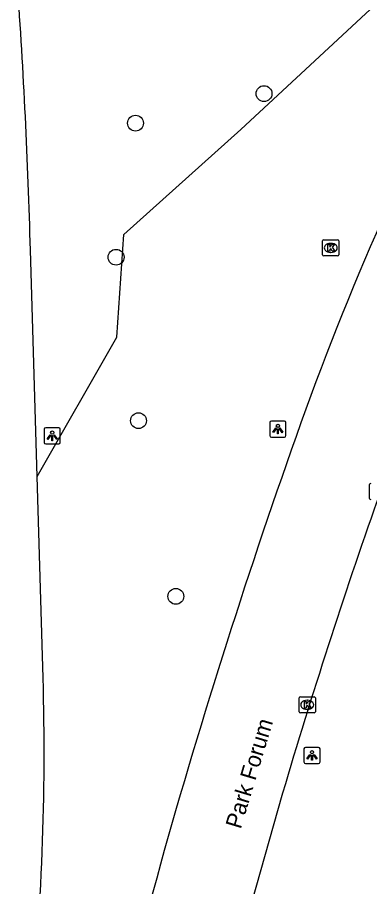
# Model space of a CAD drawing. Extents: x 154324 to 155743, y 382939 to 384183.
# Drawn here: x 155195.7 to 155217.4, y 383375.8 to 383429.5 of the extents above; entities that cross this region are included whole.
import ezdxf

# ---------------------------------------------------------------- set-up
doc = ezdxf.new("R2010")
doc.units = 0
for name, color, linetype in [('IMGEO_Boom', 7, 'Continuous'), ('IMGEO_Groenvoorziening', 7, 'Continuous'), ('IMGEO_Kolk', 7, 'Continuous'), ('IMGEO_Lichtpunt', 7, 'Continuous'), ('IMGEO_Openbare_ruimte_label', 7, 'Continuous'), ('IMGEO_Rijbaan_lokaal_open', 7, 'Continuous'), ('IMGEO_Rijbaan_regionaal_gesloten', 7, 'Continuous')]:
    doc.layers.add(name, color=color, linetype=linetype)

msp = doc.modelspace()

# ---------------------------------------------------------------- linework, layer by layer
at = {"layer": 'IMGEO_Boom'}
for centre in [(155210.882, 383424.797), (155202.942, 383422.968), (155201.746, 383414.682), (155203.128, 383404.578), (155205.432, 383393.717)]:
    msp.add_circle(centre, 0.489, dxfattribs=at)
at = {"layer": 'IMGEO_Groenvoorziening'}
msp.add_lwpolyline([(155196.87, 383401.138), (155201.784, 383409.737), (155202.227, 383416.08), (155209.454, 383422.57), (155218.304, 383430.83), (155232.76, 383449.415), (155225.088, 383476.944)], dxfattribs=at)
at = {"layer": 'IMGEO_Kolk'}
for p, q in [((155214.499, 383414.836), (155214.499, 383415.688)), ((155214.574, 383415.762), (155215.426, 383415.762)), ((155215.5, 383415.688), (155215.5, 383414.836)), ((155214.987, 383415.542), (155215.012, 383415.542)), ((155215.426, 383414.762), (155214.574, 383414.762)), ((155215.01, 383414.982), (155214.985, 383414.982)), ((155217.399, 383399.775), (155217.399, 383400.627)), ((155213.049, 383386.586), (155213.049, 383387.438)), ((155213.124, 383387.512), (155213.976, 383387.512)), ((155213.537, 383387.292), (155213.562, 383387.292)), ((155214.05, 383387.438), (155214.05, 383386.586)), ((155213.56, 383386.732), (155213.535, 383386.732)), ((155213.976, 383386.512), (155213.124, 383386.512))]:
    msp.add_line(p, q, dxfattribs=at)
for points in [[(155214.499, 383414.836), (155214.499, 383415.688)], [(155214.574, 383415.762), (155215.426, 383415.762)], [(155215.5, 383415.688), (155215.5, 383414.836)], [(155214.82, 383415.462), (155214.943, 383415.462), (155214.943, 383415.311), (155215.073, 383415.462), (155215.237, 383415.462), (155215.091, 383415.311), (155215.244, 383415.062), (155215.092, 383415.062), (155215.007, 383415.226), (155214.943, 383415.159), (155214.943, 383415.062), (155214.82, 383415.062), (155214.82, 383415.462)], [(155215.426, 383414.762), (155214.574, 383414.762)], [(155217.399, 383399.775), (155217.399, 383400.627)], [(155213.049, 383386.586), (155213.049, 383387.438)], [(155213.124, 383387.512), (155213.976, 383387.512)], [(155213.37, 383387.212), (155213.493, 383387.212), (155213.493, 383387.061), (155213.623, 383387.212), (155213.787, 383387.212), (155213.641, 383387.061), (155213.794, 383386.812), (155213.642, 383386.812), (155213.557, 383386.976), (155213.493, 383386.909), (155213.493, 383386.812), (155213.37, 383386.812), (155213.37, 383387.212)], [(155214.05, 383387.438), (155214.05, 383386.586)], [(155213.976, 383386.512), (155213.124, 383386.512)]]:
    msp.add_lwpolyline(points, dxfattribs=at)
for centre, start, end in [((155214.576, 383415.686), 91.552, 178.448), ((155214.576, 383415.686), 91.552, 178.448), ((155215.424, 383415.686), 1.552, 88.448), ((155215.424, 383415.686), 1.552, 88.448), ((155214.576, 383414.838), 181.552, 268.448), ((155214.576, 383414.838), 181.552, 268.448), ((155215.424, 383414.838), 271.552, 358.448), ((155215.424, 383414.838), 271.552, 358.448), ((155217.476, 383400.625), 91.552, 178.448), ((155217.476, 383400.625), 91.552, 178.448), ((155217.476, 383399.777), 181.552, 268.448), ((155217.476, 383399.777), 181.552, 268.448), ((155213.126, 383387.436), 91.552, 178.448), ((155213.126, 383387.436), 91.552, 178.448), ((155213.974, 383387.436), 1.552, 88.448), ((155213.974, 383387.436), 1.552, 88.448), ((155213.126, 383386.588), 181.552, 268.448), ((155213.126, 383386.588), 181.552, 268.448), ((155213.974, 383386.588), 271.552, 358.448), ((155213.974, 383386.588), 271.552, 358.448)]:
    msp.add_arc(centre, 0.0765, start, end, dxfattribs=at)
for centre, major_axis, ratio, start_param, end_param in [((155214.986, 383415.262), (-0.387, 0.002), 0.722429, 4.712389, 7.853982), ((155215.011, 383415.262), (-0.39, 0.002), 0.717154, 1.570796, 4.712389), ((155213.536, 383387.012), (-0.387, 0.002), 0.722429, 4.712389, 7.853982), ((155213.561, 383387.012), (-0.39, 0.002), 0.717154, 1.570796, 4.712389)]:
    msp.add_ellipse(centre, major_axis=major_axis, ratio=ratio, start_param=start_param, end_param=end_param, dxfattribs=at)
at = {"layer": 'IMGEO_Lichtpunt'}
for p, q in [((155211.239, 383404.464), (155211.239, 383403.657)), ((155211.239, 383404.464), (155211.239, 383403.657)), ((155212.141, 383404.559), (155211.333, 383404.559)), ((155212.141, 383404.559), (155211.333, 383404.559)), ((155212.235, 383403.657), (155212.235, 383404.464)), ((155212.235, 383403.657), (155212.235, 383404.464)), ((155197.307, 383404.046), (155197.307, 383403.239)), ((155197.307, 383404.046), (155197.307, 383403.239)), ((155198.209, 383404.141), (155197.401, 383404.141)), ((155198.209, 383404.141), (155197.401, 383404.141)), ((155198.303, 383403.239), (155198.303, 383404.046)), ((155198.303, 383403.239), (155198.303, 383404.046)), ((155211.333, 383403.563), (155212.141, 383403.563)), ((155211.333, 383403.563), (155212.141, 383403.563)), ((155197.401, 383403.145), (155198.209, 383403.145)), ((155197.401, 383403.145), (155198.209, 383403.145)), ((155213.344, 383384.289), (155213.344, 383383.482)), ((155213.344, 383384.289), (155213.344, 383383.482)), ((155214.246, 383384.384), (155213.438, 383384.384)), ((155214.246, 383384.384), (155213.438, 383384.384)), ((155214.34, 383383.482), (155214.34, 383384.289)), ((155214.34, 383383.482), (155214.34, 383384.289)), ((155213.438, 383383.388), (155214.246, 383383.388)), ((155213.438, 383383.388), (155214.246, 383383.388))]:
    msp.add_line(p, q, dxfattribs=at)
for points in [[(155211.613, 383404.128), (155211.652, 383404.1), (155211.464, 383403.838), (155211.426, 383403.865), (155211.613, 383404.128)], [(155211.715, 383404.08), (155211.762, 383404.08), (155211.762, 383403.758), (155211.715, 383403.758), (155211.715, 383404.08)], [(155211.825, 383404.1), (155211.863, 383404.127), (155212.05, 383403.865), (155212.011, 383403.837), (155211.825, 383404.1)], [(155197.681, 383403.71), (155197.72, 383403.682), (155197.532, 383403.42), (155197.494, 383403.447), (155197.681, 383403.71)], [(155197.783, 383403.662), (155197.83, 383403.662), (155197.83, 383403.34), (155197.783, 383403.34), (155197.783, 383403.662)], [(155197.893, 383403.682), (155197.931, 383403.709), (155198.118, 383403.447), (155198.079, 383403.419), (155197.893, 383403.682)], [(155213.718, 383383.953), (155213.757, 383383.925), (155213.569, 383383.663), (155213.531, 383383.69), (155213.718, 383383.953)], [(155213.82, 383383.905), (155213.867, 383383.905), (155213.867, 383383.583), (155213.82, 383383.583), (155213.82, 383383.905)], [(155213.93, 383383.925), (155213.968, 383383.952), (155214.155, 383383.69), (155214.116, 383383.662), (155213.93, 383383.925)]]:
    msp.add_lwpolyline(points, dxfattribs=at)
for centre in [(155197.806, 383403.844), (155211.738, 383404.262), (155213.843, 383384.087)]:
    msp.add_circle(centre, 0.0994, dxfattribs=at)
for centre, start, end in [((155211.333, 383404.464), 90, 180), ((155211.333, 383404.464), 90, 180), ((155212.141, 383404.464), 0, 90), ((155212.141, 383404.464), 0, 90), ((155197.401, 383404.046), 90, 180), ((155197.401, 383404.046), 90, 180), ((155198.209, 383404.046), 0, 90), ((155198.209, 383404.046), 0, 90), ((155211.333, 383403.657), 180, 270), ((155211.333, 383403.657), 180, 270), ((155212.141, 383403.657), 270, 0), ((155212.141, 383403.657), 270, 360), ((155197.401, 383403.239), 180, 270), ((155197.401, 383403.239), 180, 270), ((155198.209, 383403.239), 270, 0), ((155198.209, 383403.239), 270, 360), ((155213.438, 383384.289), 90, 180), ((155213.438, 383384.289), 90, 180), ((155214.246, 383384.289), 0, 90), ((155214.246, 383384.289), 0, 90), ((155213.438, 383383.482), 180, 270), ((155213.438, 383383.482), 180, 270), ((155214.246, 383383.482), 270, 0), ((155214.246, 383383.482), 270, 360)]:
    msp.add_arc(centre, 0.0946, start, end, dxfattribs=at)
at = {"layer": 'IMGEO_Rijbaan_lokaal_open'}
msp.add_lwpolyline([(155212.028, 383381.558), (155209.577, 383372.88)], dxfattribs=at)
for centre, radius, start, end in [((155387.616, 383342.18), 185.232, 151.172, 160.08181), ((155598.09, 383266.96), 408.742, 160.21976, 164.23418), ((155581.144, 383272.375), 384.925, 160.68698, 163.52201), ((155646.967, 383256.514), 458.63, 164.63735, 168.20821)]:
    msp.add_arc(centre, radius, start, end, dxfattribs=at)
at = {"layer": 'IMGEO_Rijbaan_regionaal_gesloten'}
for points in [[(155196.87, 383401.138), (155196.461, 383415.12)], [(155197.195, 383390.033), (155196.87, 383401.138)]]:
    msp.add_lwpolyline(points, dxfattribs=at)
for centre, radius, start, end in [((154803.457, 383404.194), 393.155, 1.59243, 4.00445), ((155039.21, 383384.136), 158.095, 354.33172, 2.13769)]:
    msp.add_arc(centre, radius, start, end, dxfattribs=at)

# ---------------------------------------------------------------- texts
at = {"layer": 'IMGEO_Openbare_ruimte_label'}
msp.add_text('Park Forum', height=1, rotation=73.2678, dxfattribs=at).set_placement((155209.439, 383379.293))

doc.saveas('drawing.dxf')
